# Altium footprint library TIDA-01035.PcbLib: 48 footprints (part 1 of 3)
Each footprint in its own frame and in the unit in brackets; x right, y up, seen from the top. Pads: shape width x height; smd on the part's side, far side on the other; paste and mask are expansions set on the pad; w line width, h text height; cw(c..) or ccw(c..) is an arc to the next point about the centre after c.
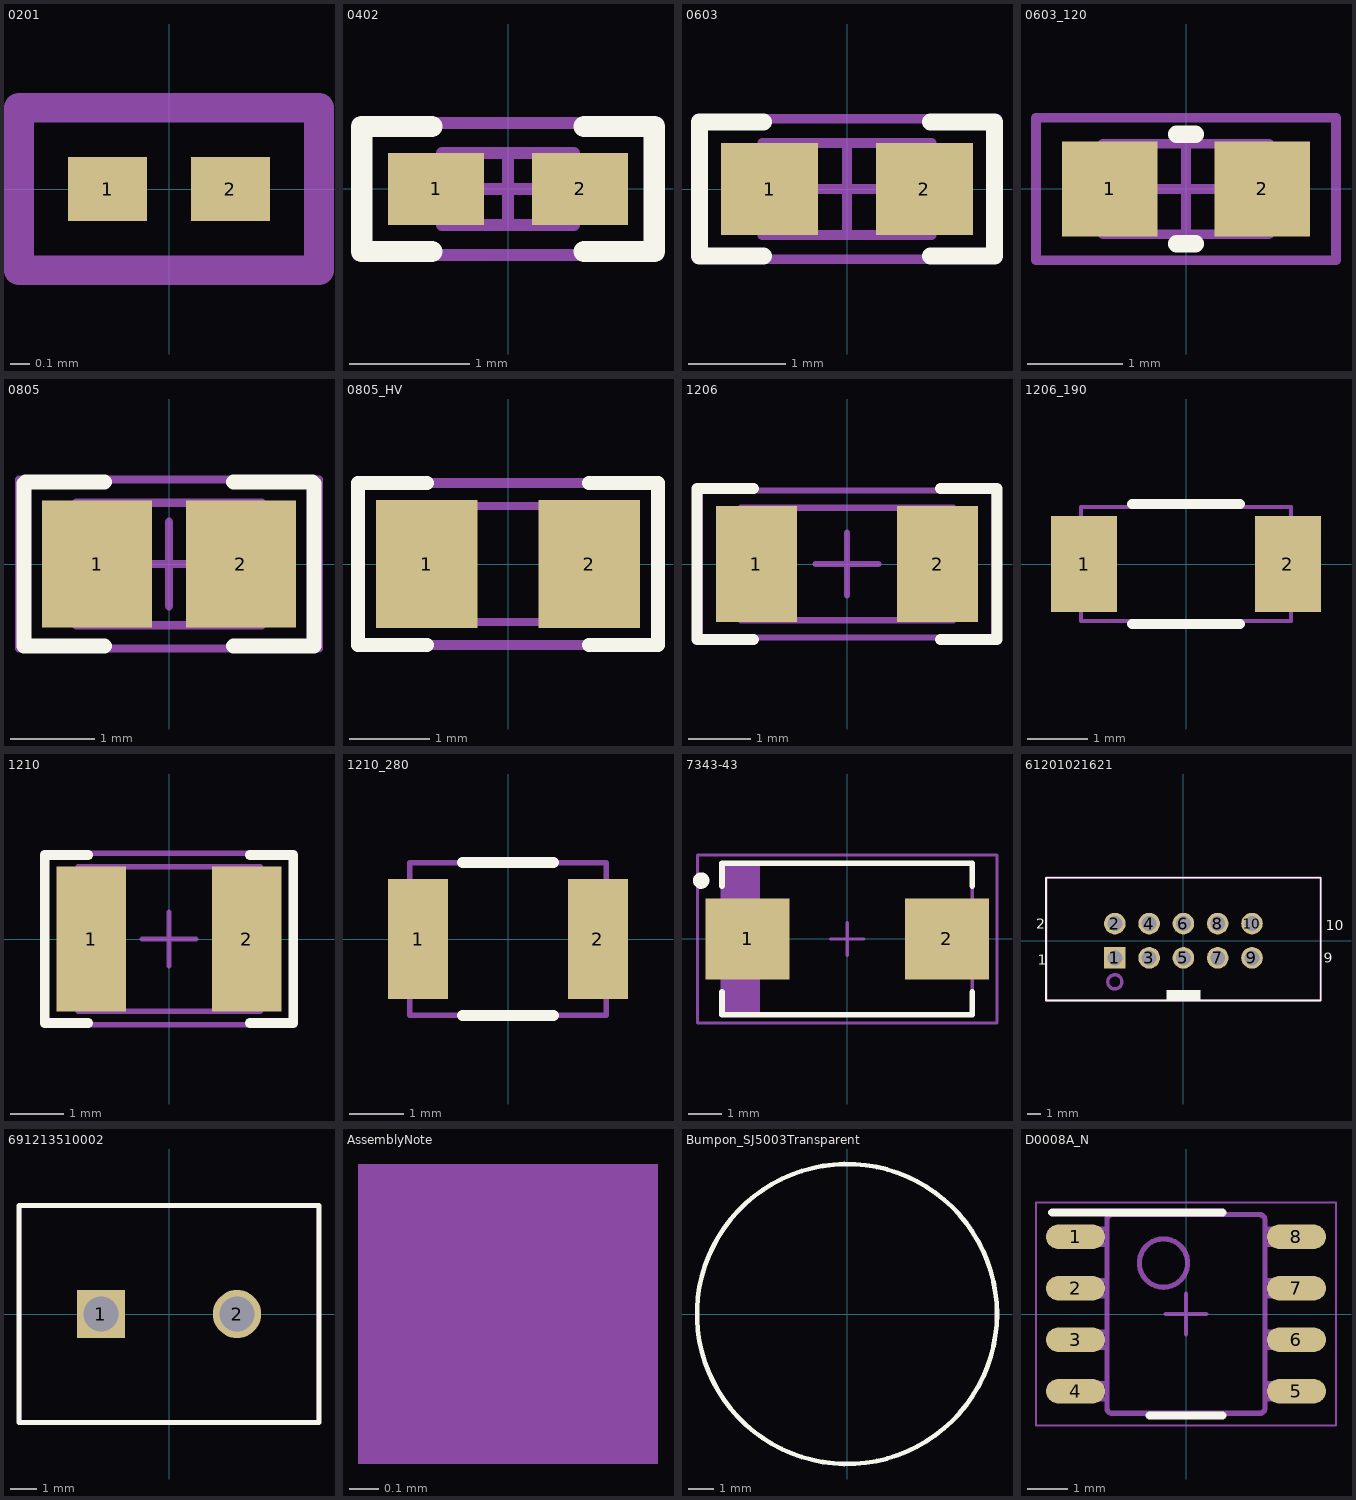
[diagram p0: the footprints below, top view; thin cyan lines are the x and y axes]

## 0201 [mil]
pads (2):
  rect 16x13 smd: 1(-12.5,0) 2(12.5,0)
Mechanical 5:
  lines w6: -30.5,-16.5 30.5,-16.5 30.5,16.5 -30.5,16.5 -30.5,-16.5
  text ".designator" at 0,0 h60
Mechanical 13:
  circle w0: c-7.5,0 r3
Mechanical 15:
  lines w6: -30.5,-16.5 30.5,-16.5 30.5,16.5 -30.5,16.5 -30.5,-16.5

## 0402 [mm] "0402 from SM-752 data"
height 0.6
pads (2):
  rect 0.8x0.6 smd: 1(-0.6,0) 2(0.6,0)
Top Overlay:
  lines w0.178: -0.635,-0.521 -1.219,-0.521 -1.219,0.521 -0.635,0.521 ; 0.635,-0.521 1.219,-0.521 1.219,0.521 0.635,0.521
Mechanical 5:
  lines w0.1: -1.25,-0.55 -1.25,0.55 1.25,0.55 1.25,-0.55 -1.25,-0.55
  text ".Designator" at -1.117,-0.305 h0.61
Mechanical 13:
  lines w0.1: -0.35,-0.3 -0.35,0.3 ; 0.35,-0.3 0.35,0.3 ; -0.55,-0.3 0.55,-0.3 0.55,0.3 -0.55,0.3 -0.55,-0.3
Mechanical 15:
  lines w0.1: -0.3,0 0.3,0 ; 0,-0.3 0,0.3 ; -1.25,-0.55 1.25,-0.55 1.25,0.55 -1.25,0.55 -1.25,-0.55
3D body: height 0.6, standoff 0, extent 0.351,-0.299 0.549,0.299
3D body: height 0.6, standoff 0, extent -0.349,-0.299 0.349,0.299
3D body: height 0.6, standoff 0, extent -0.549,-0.299 -0.351,0.299

## 0603 [mm] "0603 from SM-752 data"
height 1
pads (2):
  rect 1x0.95 smd: 1(-0.8,0) 2(0.8,0)
Top Overlay:
  lines w0.178: -0.864,-0.691 -1.524,-0.691 -1.524,0.693 -0.864,0.693 ; 0.864,-0.691 1.524,-0.691 1.524,0.693 0.864,0.693
Mechanical 5:
  lines w0.1: -1.55,-0.725 1.55,-0.725 1.55,0.725 -1.55,0.725 -1.55,-0.725
  text ".Designator" at -1.397,-0.381 h0.76
Mechanical 13:
  lines w0.1: -0.55,-0.475 -0.55,0.475 ; 0.55,-0.475 0.55,0.475 ; -0.875,-0.475 -0.875,0.475 0.875,0.475 0.875,-0.475 -0.875,-0.475
Mechanical 15:
  lines w0.1: -0.475,0 0.475,0 ; 0,-0.475 0,0.475 ; -1.55,-0.725 -1.55,0.725 1.55,0.725 1.55,-0.725 -1.55,-0.725
3D body: height 1, standoff 0, extent 0.551,-0.474 0.874,0.474
3D body: height 1, standoff 0, extent -0.549,-0.474 0.549,0.474
3D body: height 1, standoff 0, extent -0.874,-0.474 -0.551,0.474

## 0603_120 [mm] "0603_120"
height 1.2
pads (2):
  rect 1x1 smd: 1(-0.8,0) 2(0.8,0)
Top Overlay:
  lines w0.18: -0.1,-0.575 0.1,-0.575 ; -0.1,0.575 0.1,0.575
Mechanical 5:
  lines w0.1: -0.875,-0.475 -0.875,0.475 0.875,0.475 0.875,-0.475 -0.875,-0.475
  text ".Designator" at -0.725,-0.2 h0.41
Mechanical 15:
  lines w0.1: -0.475,0 0.475,0 ; 0,-0.475 0,0.475 ; -1.575,-0.75 -1.575,0.75 1.575,0.75 1.575,-0.75 -1.575,-0.75
3D body: height 1.2, standoff 0, extent 0.475,-0.475 0.875,0.475
3D body: height 1.2, standoff 0, extent -0.875,-0.475 -0.475,0.475
3D body: height 1.2, standoff 0, extent -0.475,-0.475 0.475,0.475

## 0805 [mm] "0805 from SM-752 data"
height 1.45
pads (2):
  rect 1.3x1.5 smd: 1(-0.85,0) 2(0.85,0)
Top Overlay:
  lines w0.178: -0.762,-0.968 -1.717,-0.968 -1.717,0.95 -1.699,0.968 -0.762,0.968 ; 0.762,-0.968 1.717,-0.968 1.717,0.95 1.699,0.968 0.762,0.968
Mechanical 5:
  lines w0.1: -1.775,-1 1.775,-1 1.775,1 -1.775,1 -1.775,-1
  text ".Designator" at -1.525,-0.425 h0.81
Mechanical 13:
  lines w0.1: -0.65,-0.725 -0.65,0.725 ; 0.65,-0.725 0.65,0.725 ; -1.1,-0.725 1.1,-0.725 1.1,0.725 -1.1,0.725 -1.1,-0.725
Mechanical 15:
  lines w0.1: -0.5,0 0.5,0 ; 0,-0.5 0,0.5 ; -1.775,-1 1.775,-1 1.775,1 -1.775,1 -1.775,-1
3D body: height 1.45, standoff 0, extent -1.099,-0.724 -0.651,0.724
3D body: height 1.45, standoff 0, extent -0.649,-0.724 0.649,0.724
3D body: height 1.45, standoff 0, extent 0.651,-0.724 1.099,0.724

## 0805_HV [mil] "0805 with 30mil clearance between pads"
height 57.09
pads (2):
  rect 50x63 smd: 1(-40,0) 2(40,0)
Top Overlay:
  lines w7: -40,-40 -74,-40 -74,0 -74,40 -40,40 ; 40,-40 74,-40 74,0 74,40 40,40
Mechanical 5:
  lines w5: -74,-40 74,-40 74,40 -74,40 -74,-40
  text ".Designator" at -64,-17 h35
Mechanical 13:
  lines w3.94: -25.59,-28.54 -25.59,28.54 ; 25.59,-28.54 25.59,28.54 ; -43.31,-28.54 43.31,-28.54 43.31,28.54 -43.31,28.54 -43.31,-28.54
3D body: height 57.09, standoff 0, extent -43.29,-28.52 -25.61,28.52
3D body: height 57.09, standoff 0, extent -25.57,-28.52 25.57,28.52
3D body: height 57.09, standoff 0, extent 25.61,-28.52 43.29,28.52

## 1206 [mm] "1206 from SM-752 data"
height 1.35
pads (2):
  rect 1.3x1.85 smd: 1(-1.45,0) 2(1.45,0)
Top Overlay:
  lines w0.178: -1.5,-1.21 -2.4,-1.21 -2.4,1.21 -1.5,1.21 ; 1.5,-1.21 2.4,-1.21 2.4,1.21 1.5,1.21
Mechanical 5:
  lines w0.1: -1.7,-0.9 1.7,-0.9 1.7,0.9 -1.7,0.9 -1.7,-0.9
  text ".Designator" at -1.475,-0.4 h0.81
Mechanical 13:
  lines w0.1: -1.2,-0.9 -1.2,0.9 ; 1.2,-0.9 1.2,0.9 ; -1.7,-0.9 1.7,-0.9 1.7,0.9 -1.7,0.9 -1.7,-0.9
Mechanical 15:
  lines w0.1: -0.5,0 0.5,0 ; 0,-0.5 0,0.5 ; -2.35,-1.175 2.35,-1.175 2.35,1.175 -2.35,1.175 -2.35,-1.175
3D body: height 1.35, standoff 0, extent -1.699,-0.899 -1.201,0.899
3D body: height 1.35, standoff 0, extent -1.199,-0.899 1.199,0.899
3D body: height 1.35, standoff 0, extent 1.201,-0.899 1.699,0.899

## 1206_190 [mm] "1206_190"
height 1.9
pads (2):
  rect 1.1x1.6 smd: 1(-1.7,0) 2(1.7,0)
Top Overlay:
  lines w0.17: -0.9,-1 0.9,-1 ; -0.9,1 0.9,1
Mechanical 5:
  lines w0.07: -1.75,-0.95 -1.75,0.95 1.75,0.95 1.75,-0.95 -1.75,-0.95
  text ".Designator" at -1.5,-0.4 h0.81
3D body: height 1.9, standoff 0, extent 1.301,-0.949 1.749,0.949
3D body: height 1.9, standoff 0, extent -1.299,-0.949 1.299,0.949
3D body: height 1.9, standoff 0, extent -1.749,-0.949 -1.301,0.949

## 1210 [mm]
height 0.69
pads (2):
  rect 1.3x2.7 smd: 1(-1.45,0) 2(1.45,0)
Top Overlay:
  lines w0.178: -1.511,-1.568 -2.316,-1.568 -2.316,1.568 -1.511,1.568 ; 1.511,-1.568 2.316,-1.568 2.316,1.568 1.511,1.568
Mechanical 5:
  lines w0.1: -1.7,-1.35 1.7,-1.35 1.7,1.35 -1.7,1.35 -1.7,-1.35
  text ".Designator" at -1.4,-0.375 h0.76
Mechanical 13:
  lines w0.1: -1.2,-1.35 -1.2,1.35 ; 1.2,-1.35 1.2,1.35 ; -1.7,-1.35 -1.7,1.35 1.7,1.35 1.7,-1.35 -1.7,-1.35
Mechanical 15:
  lines w0.1: -0.5,0 0.5,0 ; 0,-0.5 0,0.5 ; -2.35,-1.6 -2.35,1.6 2.35,1.6 2.35,-1.6 -2.35,-1.6
3D body: height 1.35, standoff 0, extent -1.699,-1.349 -1.201,1.349
3D body: height 1.35, standoff 0, extent -1.199,-1.349 1.199,1.349
3D body: height 1.35, standoff 0, extent 1.201,-1.349 1.699,1.349

## 1210_280 [mm] "SMD, 2-Leads, Body 3.6x2.8mm, Height 2.8mm"
height 2.8
pads (2):
  rect 1.1x2.2 smd: 1(-1.65,0) 2(1.65,0)
Top Overlay:
  lines w0.2: -0.835,-1.4 0.835,-1.4 ; -0.835,1.4 0.835,1.4
Mechanical 5:
  lines w0.1: -1.8,-1.4 -1.8,1.4 1.8,1.4 1.8,-1.4 -1.8,-1.4
  text ".Designator" at -0.787,-0.432 h0.64
3D body: height 2.8, standoff 0, extent -1.8,-1.4 -1.6,1.4
3D body: height 2.8, standoff 0, extent -1.6,-1.4 1.6,1.4
3D body: height 2.8, standoff 0, extent 1.6,-1.4 1.8,1.4

## 7343-43 [mm] "Medium density IPC based on Kemet T495 series"
height 4.3
pads (2):
  rect 2.55x2.45 smd: 1(-3.025,0) 2(3.025,0)
Top Overlay:
  circle w0.25: c-4.439,1.775 r0.125
  lines w0.178: -3.8,-1.614 -3.8,-2.3 3.8,-2.3 3.8,-1.614 ; -3.8,1.614 -3.8,2.3 3.8,2.3 3.8,1.614
Mechanical 5:
  rectangle: -3.8,-2.3 -2.7,2.3
  lines w0.1: -2.7,-2.3 -2.7,2.3 ; -3.8,-2.3 -3.8,2.3 3.8,2.3 3.8,-2.3 -3.8,-2.3
  text ".Designator" at -1.524,-0.508 h1.02
Mechanical 15:
  lines w0.1: -0.5,0 0.5,0 ; 0,-0.5 0,0.5 ; -4.55,-2.55 -4.55,2.55 4.55,2.55 4.55,-2.55 -4.55,-2.55
3D body: height 4.3, standoff 4.3, extent -3.799,-2.299 -2.701,2.299
3D body: height 4.3, standoff 0, extent -3.8,-2.3 3.8,2.3

## 61201021621 [mm]
height 0.69
pads (10):
  rect 1.6x1.6 hole 1.1: 1(-5.08,-1.27)
  round 1.6 hole 1.1: 2(-5.08,1.27) 3(-2.54,-1.27) 4(-2.54,1.27) 5(0,-1.27) 6(0,1.27) 7(2.54,-1.27) 8(2.54,1.27) 9(5.08,-1.27) 10(5.08,1.27)
Top Overlay:
  rectangle: -1.27,-4.425 1.27,-3.64
  lines w0.127: -10.18,4.55 -10.18,-4.425 ; 10.18,4.55 10.18,-4.425 ; -10.18,-4.425 -10.18,4.675 ; -10.18,-4.425 10.18,-4.425 ; -10.18,-4.425 10.18,-4.425 ; -10.18,4.675 10.18,4.675 ; -10.18,4.675 10.18,4.675 ; 10.18,-4.425 10.18,4.675
  text "2" at -10.922,0.889 h0.76
  text "9" at 10.414,-1.651 h0.76
  text "1" at -10.795,-1.778 h0.76
  text "10" at 10.541,0.762 h0.76
Mechanical 5:
  circle w0.254: c-5.08,-3.048 r0.524
  lines w0.152: -10.16,-4.445 -10.16,4.699 10.16,4.699 10.16,-4.445 -10.16,-4.445
  text ".designator" at 0,0 h0.64
3D body: height 9.13, standoff -2.98, extent -10.18,-4.425 10.18,4.75

## 691213510002 [mm] "Serie 2135 - 5.08 mm _ 2 pins"
height 10
pads (2):
  rect 1.8x1.8 hole 1.3: 1(-2.54,0)
  round 1.8 hole 1.3: 2(2.54,0)
Top Overlay:
  lines w0.2: -5.6,-4.05 -5.6,4.05 5.6,4.05 5.6,-4.05 -5.6,-4.05
Mechanical 5:
  circle w0.254: c-2.54,0 r0.524
  lines w0.152: -5.588,-4.064 5.588,-4.064 5.588,4.064 -5.588,4.064 -5.588,-4.064
  text ".designator" at 0,0 h0.64
3D body: height 10.1, standoff -3.4, extent -5.68,-4 5.68,4.1

## AssemblyNote [mm] "Assembly Note"
Mechanical 5:
  rectangle: -34.798,-67.335 -33.782,-66.319
  text ".Comment" at -33.147,-67.335 h0.76
  text ".Designator" at -38.481,-67.335 h0.76

## Bumpon_SJ5003Transparent [mil] "3M Hemispherical Bumpon transparent"
height 200
pads (1):
  round 1 on Mech3: 0(0,0)
Top Overlay:
  circle w7: c0,0 r228.04
Mechanical 5:
  circle w5: c0,0 r228.04
  text ".Designator" at -60,-20 h40
3D body: height 196.82, standoff 0, extent -216.77,-218.07 218.51,218.08

## D0008A_N [mm] "SOIC, 8-Leads, Body 4.9x3.9mm, Pitch 1.27mm, IPC Medium Density"
height 1.75
pads (8):
  oval 1.45x0.6 smd: 1(-2.725,1.905) 2(-2.725,0.635) 3(-2.725,-0.635) 4(-2.725,-1.905) 5(2.725,-1.905) 6(2.725,-0.635) 7(2.725,0.635) 8(2.725,1.905)
Top Overlay:
  lines w0.2: -3.3,2.5 0.9,2.5 ; -0.9,-2.5 0.9,-2.5
Mechanical 5:
  lines w0.127: -2.375,-2.095 -2.375,-1.715 ; -2.375,-2.095 -2.589,-2.095 -3.002,-2.095 -3.002,-1.715 -2.589,-1.715 -2.375,-1.715 ; -2.375,-2.095 -1.995,-2.095 -1.952,-2.095 -1.952,-1.715 -1.995,-1.715 -2.375,-1.715 ; -2.375,-0.825 -2.375,-0.445 ; -2.375,-0.825 -2.589,-0.825 -3.002,-0.825 -3.002,-0.445 -2.589,-0.445 -2.375,-0.445 ; -2.375,-0.825 -1.995,-0.825 -1.952,-0.825 -1.952,-0.445 -1.995,-0.445 -2.375,-0.445 ; -2.375,0.445 -2.375,0.825 ; -2.375,0.445 -2.589,0.445 -3.002,0.445 -3.002,0.825 -2.589,0.825 -2.375,0.825 ; -2.375,0.445 -1.995,0.445 -1.952,0.445 -1.952,0.825 -1.995,0.825 -2.375,0.825 ; -2.375,1.715 -2.375,2.095 ; -2.375,1.715 -2.589,1.715 -3.002,1.715 -3.002,2.095 -2.589,2.095 -2.375,2.095 ; -2.375,1.715 -1.995,1.715 -1.952,1.715 -1.952,2.095 -1.995,2.095 -2.375,2.095 ; -0.332,-2.45 -0.182,-2.45 ; -0.332,-2.45 -0.182,-2.45 ; -0.332,-2.45 -1.825,-2.45 -1.826,-2.45 cw(c-1.825,-2.323) -1.952,-2.324 -1.952,-2.323 -1.952,2.323 -1.952,2.324 cw(c-1.825,2.323) -1.826,2.45 -1.825,2.45 -0.332,2.45 ; -0.332,2.45 -0.182,2.45 ; -0.332,2.45 -0.182,2.45 ; -0.182,-2.45 0.178,-2.45 ; -0.182,2.45 0.178,2.45 ; 0.178,-2.45 0.328,-2.45 ; 0.178,-2.45 0.328,-2.45 ; 0.178,2.45 0.328,2.45 ; 0.178,2.45 0.328,2.45 ; 0.328,-2.45 1.821,-2.45 1.822,-2.45 ccw(c1.821,-2.323) 1.948,-2.324 1.948,-2.323 1.948,2.323 1.948,2.324 ccw(c1.821,2.323) 1.822,2.45 1.821,2.45 0.328,2.45 ; 2.371,-2.095 2.371,-1.715 ; 2.371,-2.095 1.991,-2.095 1.948,-2.095 1.948,-1.715 1.991,-1.715 2.371,-1.715 ; 2.371,-2.095 2.585,-2.095 2.998,-2.095 2.998,-1.715 2.585,-1.715 2.371,-1.715 ; 2.371,-0.825 2.371,-0.445 ; 2.371,-0.825 1.991,-0.825 1.948,-0.825 1.948,-0.445 1.991,-0.445 2.371,-0.445 ; 2.371,-0.825 2.585,-0.825 2.998,-0.825 2.998,-0.445 2.585,-0.445 2.371,-0.445 ; 2.371,0.445 2.371,0.825 ; 2.371,0.445 1.991,0.445 1.948,0.445 1.948,0.825 1.991,0.825 2.371,0.825 ; 2.371,0.445 2.585,0.445 2.998,0.445 2.998,0.825 2.585,0.825 2.371,0.825 ; 2.371,1.715 2.371,2.095 ; 2.371,1.715 1.991,1.715 1.948,1.715 1.948,2.095 1.991,2.095 2.371,2.095 ; 2.371,1.715 2.585,1.715 2.998,1.715 2.998,2.095 2.585,2.095 2.371,2.095 ; -0.555,0.659 ccw(c-0.555,1.256) -0.555,1.853 ccw(c-0.555,1.256) -0.555,0.659
  text ".Designator" at -1.625,-0.625 h0.89
Mechanical 15:
  lines w0.05: -3.7,-2.75 -3.7,2.75 3.7,2.75 3.7,-2.75 -3.7,-2.75
  lines w0.1: -0.5,0 0.5,0 ; 0,-0.5 0,0.5
3D body: height 1.63, standoff 0, extent -3,-2.45 3,2.45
